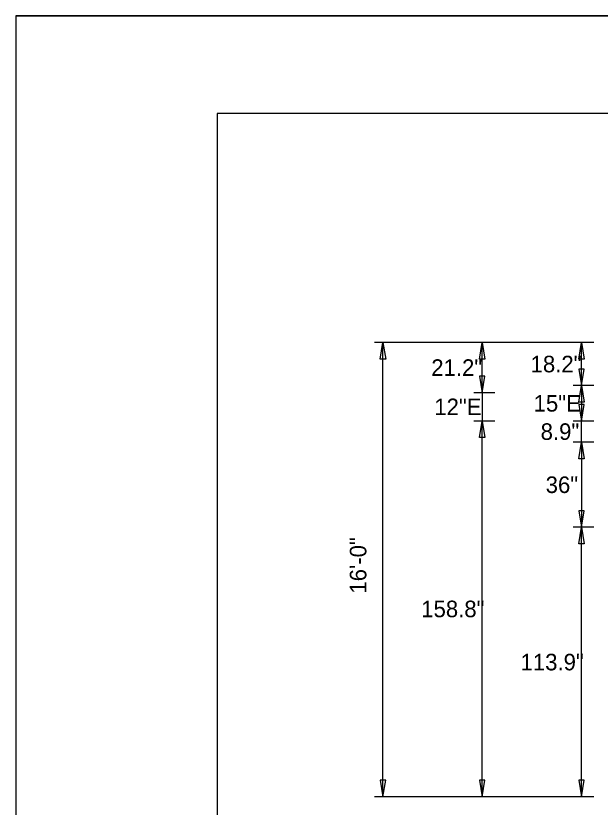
# Model space of a CAD drawing. Extents: x 2150010 to 2150174, y 145114 to 145224.
# Drawn here: x 2150010.46 to 2150031.05, y 145192.08 to 145219.95 of the extents above; entities that cross this region are included whole.
import ezdxf

# ---------------------------------------------------------------- set-up
doc = ezdxf.new("R2010")
doc.units = 0
for name, color, linetype in [('BORDER', 7, 'Continuous'), ('GSDIMS', 7, 'Continuous'), ('PDF', 7, 'Continuous')]:
    doc.layers.add(name, color=color, linetype=linetype)

msp = doc.modelspace()

# ---------------------------------------------------------------- linework, layer by layer
at = {"layer": 'BORDER'}
for p, q in [((2150010.458, 145219.948), (2150174.061, 145219.948)), ((2150010.458, 145219.948), (2150010.458, 145114.088)), ((2150171.536, 145216.512), (2150017.557, 145216.512)), ((2150017.557, 145216.512), (2150017.557, 145117.388))]:
    msp.add_line(p, q, dxfattribs=at)
at = {"layer": 'GSDIMS'}
for p, q in [((2150023.833, 145208.445), (2150023.103, 145208.445)), ((2150023.395, 145192.445), (2150023.395, 145208.445)), ((2150030.833, 145208.445), (2150023.833, 145208.445)), ((2150027.333, 145208.445), (2150026.603, 145208.445)), ((2150026.895, 145206.677), (2150026.895, 145208.445)), ((2150030.833, 145208.445), (2150030.103, 145208.445)), ((2150030.395, 145206.927), (2150030.395, 145208.445)), ((2150030.833, 145206.927), (2150030.103, 145206.927)), ((2150030.833, 145206.927), (2150030.103, 145206.927)), ((2150030.395, 145206.927), (2150030.395, 145205.677)), ((2150027.333, 145206.677), (2150026.603, 145206.677)), ((2150027.333, 145206.677), (2150026.603, 145206.677)), ((2150026.895, 145206.677), (2150026.895, 145205.677)), ((2150027.333, 145205.677), (2150026.603, 145205.677)), ((2150027.333, 145205.677), (2150026.603, 145205.677)), ((2150026.895, 145192.445), (2150026.895, 145205.677)), ((2150030.833, 145205.677), (2150030.103, 145205.677)), ((2150030.833, 145205.677), (2150030.103, 145205.677)), ((2150030.395, 145204.935), (2150030.395, 145205.677)), ((2150030.833, 145204.935), (2150030.103, 145204.935)), ((2150030.833, 145204.935), (2150030.103, 145204.935)), ((2150030.395, 145204.935), (2150030.395, 145201.935)), ((2150030.833, 145201.935), (2150030.103, 145201.935)), ((2150030.833, 145201.935), (2150030.103, 145201.935)), ((2150030.395, 145192.445), (2150030.395, 145201.935)), ((2150023.833, 145192.445), (2150023.103, 145192.445)), ((2150030.833, 145192.445), (2150023.833, 145192.445)), ((2150027.333, 145192.445), (2150026.603, 145192.445)), ((2150030.833, 145192.445), (2150030.103, 145192.445))]:
    msp.add_line(p, q, dxfattribs=at)
for points in [[(2150023.395, 145208.445), (2150023.492, 145207.861), (2150023.298, 145207.861)], [(2150026.895, 145208.445), (2150026.992, 145207.861), (2150026.798, 145207.861)], [(2150030.395, 145208.445), (2150030.492, 145207.861), (2150030.298, 145207.861)], [(2150030.395, 145206.927), (2150030.492, 145207.51), (2150030.298, 145207.51)], [(2150026.895, 145206.677), (2150026.992, 145207.26), (2150026.798, 145207.26)], [(2150030.395, 145206.927), (2150030.492, 145206.343), (2150030.298, 145206.343)], [(2150030.395, 145205.677), (2150030.492, 145206.26), (2150030.298, 145206.26)], [(2150026.895, 145205.677), (2150026.992, 145205.093), (2150026.798, 145205.093)], [(2150030.395, 145204.935), (2150030.492, 145204.352), (2150030.298, 145204.352)], [(2150030.395, 145201.935), (2150030.492, 145202.518), (2150030.298, 145202.518)], [(2150030.395, 145201.935), (2150030.492, 145201.352), (2150030.298, 145201.352)], [(2150023.395, 145192.445), (2150023.492, 145193.028), (2150023.298, 145193.028)], [(2150026.895, 145192.445), (2150026.992, 145193.028), (2150026.798, 145193.028)], [(2150030.395, 145192.445), (2150030.492, 145193.028), (2150030.298, 145193.028)]]:
    msp.add_lwpolyline(points, close=True, dxfattribs=at)
at = {"layer": 'PDF'}
msp.add_lwpolyline([(2150010.458, 145114.088), (2150174.061, 145114.088), (2150174.061, 145219.948), (2150010.458, 145219.948)], close=True, dxfattribs=at)

# ---------------------------------------------------------------- texts
at = {"layer": 'GSDIMS'}
for s, p in [('18.2"', (2150028.599, 145207.394)), ('21.2"', (2150025.099, 145207.269)), ('15"E', (2150028.705, 145206.01)), ('12"E', (2150025.205, 145205.885)), ('8.9"', (2150028.953, 145205.014)), ('36"', (2150029.13, 145203.143)), ('158.8"', (2150024.745, 145198.769)), ('113.9"', (2150028.245, 145196.898))]:
    msp.add_text(s, height=0.5833, dxfattribs=at).set_placement(p)
msp.add_text('16\'-0"', height=0.5833, rotation=90, dxfattribs=at).set_placement((2150022.812, 145199.6))

doc.saveas('drawing.dxf')
